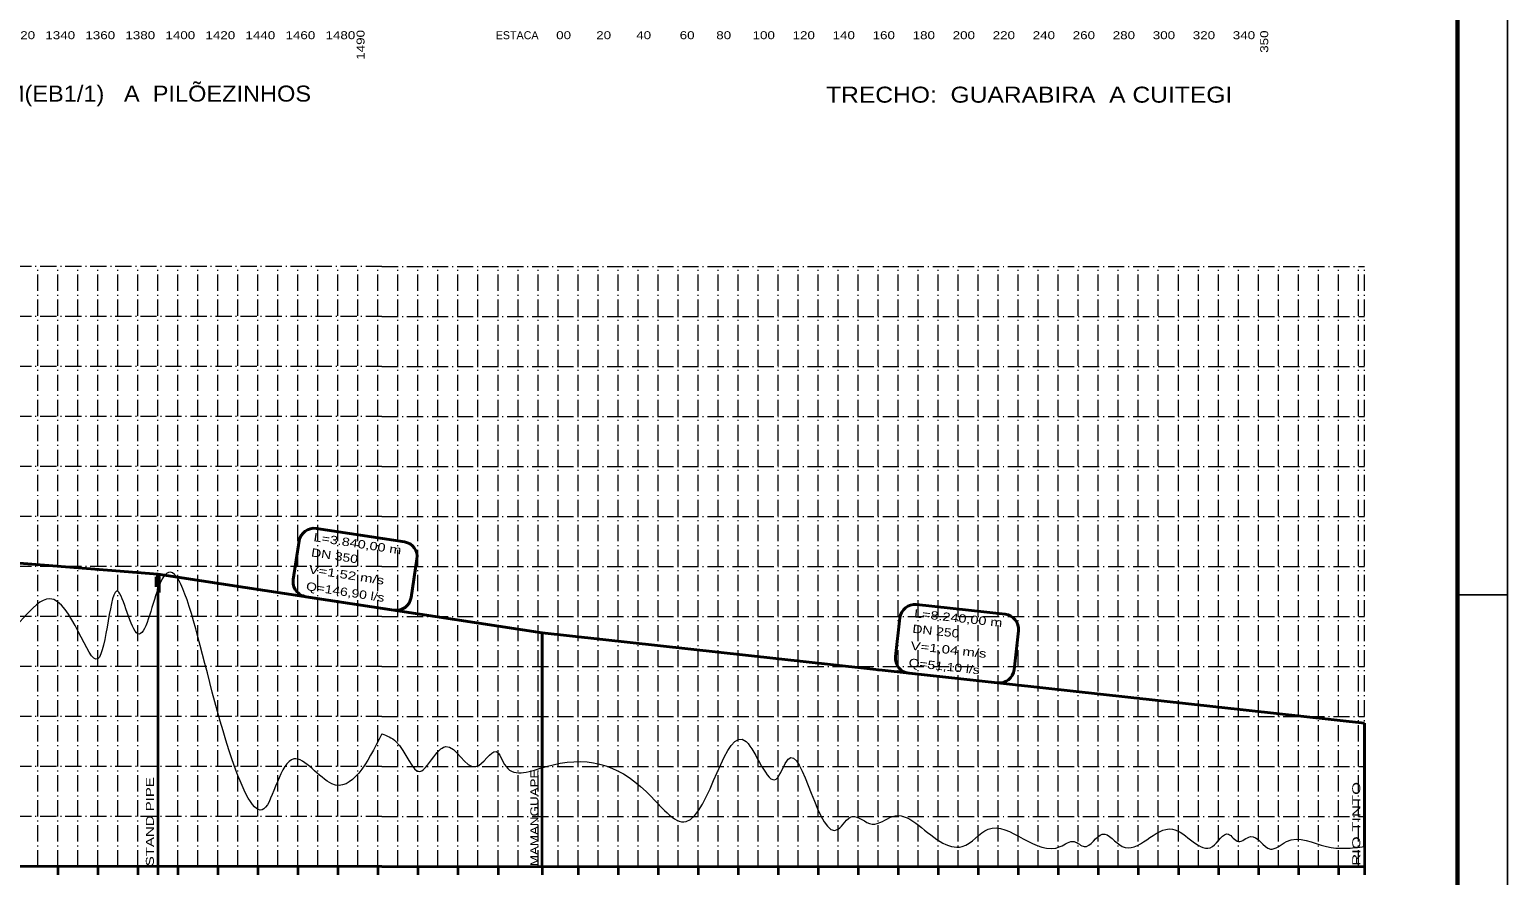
# Model space of a CAD drawing. Extents: x 0 to 1772, y 0 to 1188.
# Drawn here: x 1181 to 1772, y 482 to 820 of the extents above; entities that cross this region are included whole.
import ezdxf
from ezdxf.enums import TextEntityAlignment as Align

# ---------------------------------------------------------------- set-up
doc = ezdxf.new("R2010")
doc.units = 0
doc.header["$LTSCALE"] = 1.3
doc.linetypes.add('DOT_DASHED', pattern=[7.7, 5, -1.2, 0.3, -1.2])
for name, color, linetype, lineweight in [('1', 7, 'DOT_DASHED', 13), ('24', 7, 'Continuous', 35), ('56', 7, 'Continuous', 13), ('62', 7, 'Continuous', 13), ('63', 7, 'Continuous', 25), ('7', 7, 'Continuous', 35), ('9', 7, 'Continuous', 40)]:
    doc.layers.add(name, color=color, linetype=linetype, lineweight=lineweight)

msp = doc.modelspace()

# ---------------------------------------------------------------- linework, layer by layer
at = {"layer": '1'}
for p, q in [((1321.857, 725.251), (913.857, 725.251)), ((1184.257, 485.251), (1184.257, 725.251)), ((1192.257, 485.251), (1192.257, 725.251)), ((1200.257, 485.251), (1200.257, 725.251)), ((1208.257, 485.251), (1208.257, 725.251)), ((1216.257, 485.251), (1216.257, 725.251)), ((1224.257, 485.251), (1224.257, 725.251)), ((1232.257, 485.251), (1232.257, 725.251)), ((1240.257, 485.251), (1240.257, 725.251)), ((1248.257, 485.251), (1248.257, 725.251)), ((1256.257, 485.251), (1256.257, 725.251)), ((1264.257, 485.251), (1264.257, 725.251)), ((1272.257, 485.251), (1272.257, 725.251)), ((1280.257, 485.251), (1280.257, 725.251)), ((1288.257, 485.251), (1288.257, 725.251)), ((1296.257, 485.251), (1296.257, 725.251)), ((1304.257, 485.251), (1304.257, 725.251)), ((1312.257, 485.251), (1312.257, 725.251)), ((1320.257, 485.251), (1320.257, 725.251)), ((1321.857, 725.251), (1714.657, 725.251)), ((1328.257, 485.251), (1328.257, 725.251)), ((1336.257, 485.251), (1336.257, 725.251)), ((1344.257, 485.251), (1344.257, 725.251)), ((1352.257, 485.251), (1352.257, 725.251)), ((1360.257, 485.251), (1360.257, 725.251)), ((1368.257, 485.251), (1368.257, 725.251)), ((1376.257, 485.251), (1376.257, 725.251)), ((1384.257, 485.251), (1384.257, 725.251)), ((1392.257, 485.251), (1392.257, 725.251)), ((1400.257, 485.251), (1400.257, 725.251)), ((1408.257, 485.251), (1408.257, 725.251)), ((1416.257, 485.251), (1416.257, 725.251)), ((1424.257, 485.251), (1424.257, 725.251)), ((1432.257, 485.251), (1432.257, 725.251)), ((1440.257, 485.251), (1440.257, 725.251)), ((1448.257, 485.251), (1448.257, 725.251)), ((1456.257, 485.251), (1456.257, 725.251)), ((1464.257, 485.251), (1464.257, 725.251)), ((1472.257, 485.251), (1472.257, 725.251)), ((1480.257, 485.251), (1480.257, 725.251)), ((1488.257, 485.251), (1488.257, 725.251)), ((1496.257, 485.251), (1496.257, 725.251)), ((1504.257, 485.251), (1504.257, 725.251)), ((1512.257, 485.251), (1512.257, 725.251)), ((1520.257, 485.251), (1520.257, 725.251)), ((1528.257, 485.251), (1528.257, 725.251)), ((1536.257, 485.251), (1536.257, 725.251)), ((1544.257, 485.251), (1544.257, 725.251)), ((1552.257, 485.251), (1552.257, 725.251)), ((1560.257, 485.251), (1560.257, 725.251)), ((1568.257, 485.251), (1568.257, 725.251)), ((1576.257, 485.251), (1576.257, 725.251)), ((1584.257, 485.251), (1584.257, 725.251)), ((1592.257, 485.251), (1592.257, 725.251)), ((1600.257, 485.251), (1600.257, 725.251)), ((1608.257, 485.251), (1608.257, 725.251)), ((1616.257, 485.251), (1616.257, 725.251)), ((1624.257, 485.251), (1624.257, 725.251)), ((1632.257, 485.251), (1632.257, 725.251)), ((1640.257, 485.251), (1640.257, 725.251)), ((1648.257, 485.251), (1648.257, 725.251)), ((1656.257, 485.251), (1656.257, 725.251)), ((1664.257, 485.251), (1664.257, 725.251)), ((1672.257, 485.251), (1672.257, 725.251)), ((1680.257, 485.251), (1680.257, 725.251)), ((1688.257, 485.251), (1688.257, 725.251)), ((1696.257, 485.251), (1696.257, 725.251)), ((1704.257, 485.251), (1704.257, 725.251)), ((1712.257, 485.251), (1712.257, 725.251)), ((1714.657, 485.251), (1714.657, 725.251)), ((1321.857, 705.251), (913.857, 705.251)), ((1321.857, 705.251), (1714.657, 705.251)), ((1321.857, 685.251), (913.857, 685.251)), ((1321.857, 685.251), (1714.657, 685.251)), ((1321.857, 665.251), (913.857, 665.251)), ((1321.857, 665.251), (1714.657, 665.251)), ((1321.857, 645.251), (913.857, 645.251)), ((1321.857, 645.251), (1714.657, 645.251)), ((1321.857, 625.251), (913.857, 625.251)), ((1321.857, 625.251), (1714.657, 625.251)), ((1321.857, 605.251), (913.857, 605.251)), ((1321.857, 605.251), (1714.657, 605.251)), ((1321.857, 585.251), (913.857, 585.251)), ((1321.857, 585.251), (1714.657, 585.251)), ((1321.857, 565.251), (913.857, 565.251)), ((1321.857, 565.251), (1714.657, 565.251)), ((1321.857, 545.251), (913.857, 545.251)), ((1321.857, 545.251), (1714.657, 545.251)), ((1321.857, 525.251), (913.857, 525.251)), ((1321.857, 525.251), (1714.657, 525.251)), ((1321.857, 505.251), (913.857, 505.251)), ((1321.857, 505.251), (1714.657, 505.251))]:
    msp.add_line(p, q, dxfattribs=at)
at = {"layer": '56'}
for points in [[(1321.875, 538.34), (1301.875, 518.34), (1286.675, 528.34), (1274.675, 508.34), (1261.875, 528.34), (1232.275, 596.34), (1224.275, 578.34), (1216.275, 595.34), (1208.275, 568.34), (1189.075, 592.34), (1169.075, 578.34), (1161.875, 591.34), (1145.875, 548.34), (1137.875, 531.34), (1129.875, 543.34), (1117.875, 543.34), (1105.875, 528.34), (1089.875, 528.34), (1049.875, 588.34), (1041.875, 591.34), (1033.875, 588.34), (972.275, 578.34), (954.275, 578.84), (948.275, 580.34), (939.475, 578.34), (929.875, 573.34), (923.875, 580.328), (917.898, 584.62), (913.857, 585.251)], [(1321.856, 538.35), (1327.457, 535.251), (1337.057, 523.251), (1343.457, 530.251), (1347.457, 533.251), (1359.457, 525.251), (1367.457, 531.251), (1371.457, 525.251), (1387.457, 525.251), (1427.457, 515.251), (1443.457, 503.251), (1467.457, 535.251), (1479.457, 520.251), (1484.257, 528.251), (1504.257, 500.251), (1509.857, 505.251), (1517.857, 502.251), (1525.857, 505.251), (1545.057, 495.251), (1553.857, 493.251), (1564.257, 500.251), (1593.057, 493.251), (1598.657, 495.251), (1602.657, 493.251), (1609.857, 498.251), (1617.857, 493.251), (1637.857, 500.251), (1653.857, 493.251), (1660.257, 498.251), (1664.257, 495.251), (1669.057, 497.251), (1677.057, 492.251), (1683.457, 495.251), (1699.457, 493.251), (1714.657, 493.251)]]:
    msp.add_spline(points, degree=3, dxfattribs=at)
at = {"layer": '62', "lineweight": 35}
for p, q in [((1385.857, 485.251), (1385.857, 525.251)), ((1714.657, 493.251), (1714.657, 485.251)), ((1321.857, 485.251), (913.857, 485.251)), ((1192.257, 485.251), (1192.257, 481.901)), ((1208.257, 485.251), (1208.257, 481.901)), ((1224.257, 485.251), (1224.257, 481.901)), ((1240.257, 485.251), (1240.257, 481.901)), ((1256.257, 485.251), (1256.257, 481.901)), ((1272.257, 485.251), (1272.257, 481.901)), ((1288.257, 485.251), (1288.257, 481.901)), ((1304.257, 485.251), (1304.257, 481.901)), ((1320.257, 485.251), (1320.257, 481.901)), ((1321.857, 485.251), (1714.657, 485.251)), ((1336.257, 485.251), (1336.257, 481.901)), ((1352.257, 485.251), (1352.257, 481.901)), ((1368.257, 485.251), (1368.257, 481.901)), ((1385.857, 485.251), (1385.857, 481.901)), ((1400.257, 485.251), (1400.257, 481.901)), ((1416.257, 485.251), (1416.257, 481.901)), ((1432.257, 485.251), (1432.257, 481.901)), ((1448.257, 485.251), (1448.257, 481.901)), ((1464.257, 485.251), (1464.257, 481.901)), ((1480.257, 485.251), (1480.257, 481.901)), ((1496.257, 485.251), (1496.257, 481.901)), ((1512.257, 485.251), (1512.257, 481.901)), ((1528.257, 485.251), (1528.257, 481.901)), ((1544.257, 485.251), (1544.257, 481.901)), ((1560.257, 485.251), (1560.257, 481.901)), ((1576.257, 485.251), (1576.257, 481.901)), ((1592.257, 485.251), (1592.257, 481.901)), ((1608.257, 485.251), (1608.257, 481.901)), ((1624.257, 485.251), (1624.257, 481.901)), ((1640.257, 485.251), (1640.257, 481.901)), ((1656.257, 485.251), (1656.257, 481.901)), ((1672.257, 485.251), (1672.257, 481.901)), ((1688.257, 485.251), (1688.257, 481.901)), ((1704.257, 485.251), (1704.257, 481.901)), ((1714.657, 485.251), (1714.657, 481.901))]:
    msp.add_line(p, q, dxfattribs=at)
msp.add_lwpolyline([(1232.257, 596.377), (1232.257, 485.251), (1232.257, 481.901)], dxfattribs=at)
at = {"layer": '63'}
for p, q in [((1771.833, -0.127), (1771.833, 1187.873)), ((1771.833, -0.127), (1771.833, 1187.873)), ((1751.833, 593.873), (1771.833, 593.873))]:
    msp.add_line(p, q, dxfattribs=at)
msp.add_lwpolyline([(-0.167, -0.127), (1771.833, -0.127), (1771.833, 1187.873)], dxfattribs=at)
at = {"layer": '63', "lineweight": 60}
msp.add_lwpolyline([(49.833, 1167.873), (1751.833, 1167.873), (1751.833, 19.873), (49.833, 19.873)], close=True, dxfattribs=at)
at = {"layer": '7'}
msp.add_line((1231.564, 597.169), (1231.564, 601.159), dxfattribs=at)
msp.add_lwpolyline([(1232.951, 594.922), (1232.951, 601.159), (1231.564, 601.159)], dxfattribs=at)
at = {"layer": '9'}
for p, q in [((913.857, 626.933), (1232.257, 602.251)), ((1295.625, 620.481), (1330.848, 615.087)), ((1288.786, 615.458), (1286.423, 600.027)), ((1335.871, 608.248), (1333.508, 592.817)), ((1291.446, 593.188), (1326.669, 587.795)), ((1535.568, 590.03), (1570.988, 586.132)), ((1528.948, 584.723), (1527.24, 569.206)), ((1576.296, 579.511), (1574.588, 563.995)), ((1385.857, 525.251), (1385.857, 578.731)), ((1532.547, 562.586), (1567.967, 558.687)), ((1714.657, 493.251), (1714.657, 542.541))]:
    msp.add_line(p, q, dxfattribs=at)
msp.add_lwpolyline([(1232.257, 602.251), (1385.857, 578.731), (1714.657, 542.541)], dxfattribs=at)
for centre, start, end in [((1294.717, 614.55), 81.29419, 171.29419), ((1329.94, 609.156), 351.29419, 81.29419), ((1292.354, 599.119), 171.29419, 261.29419), ((1327.577, 593.725), 261.29419, 351.29419), ((1534.912, 584.066), 83.71891, 173.71891), ((1570.332, 580.168), 353.71891, 83.71891), ((1533.204, 568.55), 173.71891, 263.71891), ((1568.624, 564.651), 263.71891, 353.71891)]:
    msp.add_arc(centre, 6, start, end, dxfattribs=at)

# ---------------------------------------------------------------- texts
at = {"layer": '24'}
for s, height, width, p in [('1320', 3.2, 1.25, (1177.24, 816.125)), ('1340', 3.2, 1.25, (1193.24, 816.125)), ('1360', 3.2, 1.25, (1209.24, 816.125)), ('1380', 3.2, 1.25, (1225.24, 816.125)), ('1400', 3.2, 1.25, (1241.24, 816.125)), ('1420', 3.2, 1.25, (1257.24, 816.125)), ('1440', 3.2, 1.25, (1273.24, 816.125)), ('1460', 3.2, 1.25, (1289.24, 816.125)), ('1480', 3.2, 1.25, (1305.24, 816.125)), ('00', 3.2, 1.25, (1394.493, 816.125)), ('20', 3.2, 1.25, (1410.493, 816.125)), ('40', 3.2, 1.25, (1426.493, 816.125)), ('60', 3.2, 1.25, (1443.866, 816.125)), ('80', 3.2, 1.25, (1458.493, 816.125)), ('100', 3.2, 1.25, (1474.493, 816.125)), ('120', 3.2, 1.25, (1490.493, 816.125)), ('140', 3.2, 1.25, (1506.493, 816.125)), ('160', 3.2, 1.25, (1522.493, 816.125)), ('180', 3.2, 1.25, (1538.493, 816.125)), ('200', 3.2, 1.25, (1554.493, 816.125)), ('220', 3.2, 1.25, (1570.493, 816.125)), ('240', 3.2, 1.25, (1586.493, 816.125)), ('260', 3.2, 1.25, (1602.493, 816.125)), ('280', 3.2, 1.25, (1618.493, 816.125)), ('300', 3.2, 1.25, (1634.493, 816.125)), ('320', 3.2, 1.25, (1650.493, 816.125)), ('340', 3.2, 1.25, (1666.493, 816.125)), ('TRECHO:  BARRAGEM(EB1/1)   A  PILÕEZINHOS', 6.4, 1.1, (1185.492, 791.171)), ('TRECHO:  GUARABIRA  A CUITEGI', 6.4, 1.15, (1580.616, 790.752))]:
    msp.add_text(s, height=height, dxfattribs=dict(at, width=width)).set_placement(p, align=Align.CENTER)
at = {"layer": '24', "width": 1.25}
for s, p in [('1490', (1314.907, 813.849)), ('350', (1676.192, 815.156))]:
    msp.add_text(s, height=3.2, rotation=90, dxfattribs=at).set_placement(p, align=Align.CENTER)
at = {"layer": '24'}
msp.add_text('ESTACA', height=3.2, dxfattribs=at).set_placement((1375.903, 816.125), align=Align.CENTER)
for s, width, p in [('STAND PIPE', 1.4, (1230.673, 485.4)), ('MAMANGUAPE', 1.25, (1384.388, 485.4)), ('RIO TINTO', 1.55, (1712.991, 485.558))]:
    msp.add_text(s, height=3.2, rotation=90, dxfattribs=dict(at, width=width)).set_placement(p)
at = {"layer": '9'}
for s, rotation, width, p in [('L=3.840,00 m', 351.294, 1.3, (1294.332, 615.44)), ('DN 350', 351.294, 1.25, (1293.396, 609.331)), ('V=1,52 m/s', 351.294, 1.35, (1292.363, 602.586)), ('Q=146,90 l/s', 351.294, 1.25, (1291.331, 595.841)), ('L=8.240,00 m', 353.719, 1.3, (1534.489, 584.939)), ('DN 250', 353.719, 1.25, (1533.813, 578.797)), ('V=1,04 m/s', 353.719, 1.35, (1533.067, 572.014)), ('Q=51,10 l/s', 353.719, 1.25, (1532.32, 565.231))]:
    msp.add_text(s, height=3.319, rotation=rotation, dxfattribs=dict(at, width=width)).set_placement(p)

doc.saveas('drawing.dxf')
